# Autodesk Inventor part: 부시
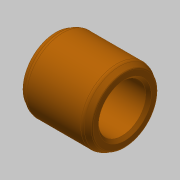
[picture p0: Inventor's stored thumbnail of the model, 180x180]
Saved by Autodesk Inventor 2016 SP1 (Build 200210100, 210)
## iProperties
Created: 2018-11
Part Number: 부시
Material: 강철, 연강
Document SubType Name: Modeling
Designer: mduedu
Density: 1 g/cm^3
Appearance: 주황색
Author: mduedu
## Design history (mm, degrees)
sketch "스케치1"
  geometry: C1 r 8.5 at (0, 0); C2 r 13 at (0, 0); 1 further point
  constraints: 2 centre point, 2 coincident
  dimensions: "d0" = 17 diameter of C1; "d1" = 26 diameter of C2
extrude "돌출1" new body sketch "스케치1" distance "d2" = 25; taper "d3" = 0 deg
chamfer "모따기4" distance "d14" = 1; stored, may be unused: second distance "d15" = 2, angle "d16" = 15 deg
chamfer "모따기5" distance "d17" = 2.3; stored, may be unused: second distance "d18" = 2, angle "d19" = 30 deg
chamfer "모따기6" distance "d20" = 2.3; stored, may be unused: second distance "d21" = 2, angle "d22" = 30 deg
fillet "모깎기2" dims "d23" = 2, "d24" = 0.5
fillet "모깎기3" dims "d25" = 2, "d26" = 0.5
node "솔리드1"
